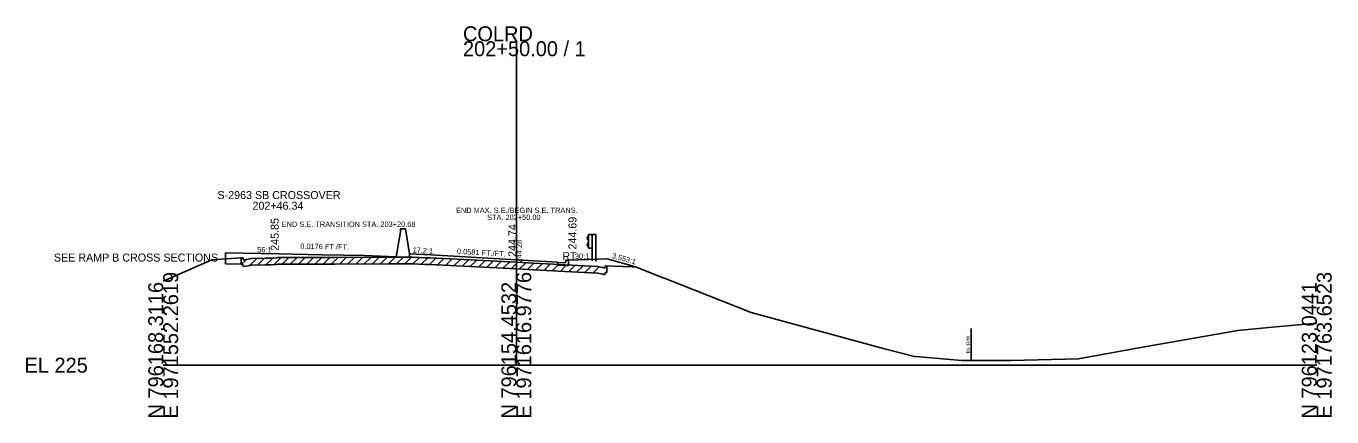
# Model space of a CAD drawing. Extents: x -26 to 1971520, y -10 to 796285.
# Drawn here: x 1274.3 to 1519, y 490.3 to 563.6 of the extents above; entities that cross this region are included whole.
import ezdxf

# ---------------------------------------------------------------- set-up
doc = ezdxf.new("R2010")
doc.units = 0
for name, color, linetype in [('RD_GPK_XS_Cell', 7, 'Continuous'), ('RD_XS_Base', 7, 'Continuous'), ('RD_XS_CurbBase', 7, 'Continuous'), ('RD_XS_CurbTop', 7, 'Continuous'), ('RD_XS_ExGround', 7, 'Continuous'), ('RD_XS_ExPaveRet', 7, 'Continuous'), ('RD_XS_ExRW', 7, 'Continuous'), ('RD_XS_GR', 7, 'Continuous'), ('RD_XS_MedBWall', 7, 'Continuous'), ('RD_XS_Misc_Line', 7, 'Continuous'), ('RD_XS_Pave', 7, 'Continuous'), ('RD_XS_PaveOvlay', 7, 'Continuous'), ('RD_XS_PaveShd', 7, 'Continuous'), ('RD_XS_TieSlope', 7, 'Continuous'), ('RD_XS_TX_Elev_EX', 7, 'Continuous'), ('RD_XS_TX_Elev_PR', 7, 'Continuous'), ('RD_XS_TX_MkPT', 7, 'Continuous'), ('RD_XS_TX_Notes', 7, 'Continuous'), ('RD_XS_TX_Slope', 7, 'Continuous'), ('RD_XS_TX_Station', 7, 'Continuous'), ('RD_XS_TX_TOC', 7, 'Continuous')]:
    doc.layers.add(name, color=color, linetype=linetype)

msp = doc.modelspace()

# ---------------------------------------------------------------- linework, layer by layer
at = {"layer": 'RD_GPK_XS_Cell'}
for p, q in [((1366.18, 500), (1366.18, 560.72)), ((1300, 500), (1366.18, 500)), ((1366.18, 500), (1516.18, 500))]:
    msp.add_line(p, q, dxfattribs=at)
at = {"layer": 'RD_XS_Base'}
for p, q in [((1311.65, 518.99), (1311.65, 521.03)), ((1314.62, 518.94), (1311.65, 518.99)), ((1373.94, 519.27), (1373.94, 519.29)), ((1373.94, 518.77), (1373.94, 519.27))]:
    msp.add_line(p, q, dxfattribs=at)
at = {"layer": 'RD_XS_CurbBase'}
for p, q in [((1375.95, 519.68), (1375.95, 518.68)), ((1375.37, 518.68), (1373.94, 518.77)), ((1375.95, 518.68), (1375.37, 518.68))]:
    msp.add_line(p, q, dxfattribs=at)
at = {"layer": 'RD_XS_CurbTop'}
for p, q in [((1373.94, 519.29), (1373.94, 519.27)), ((1373.94, 519.27), (1375.37, 519.18)), ((1375.37, 519.18), (1375.45, 519.68)), ((1375.45, 519.68), (1375.95, 519.68))]:
    msp.add_line(p, q, dxfattribs=at)
at = {"layer": 'RD_XS_ExGround'}
msp.add_lwpolyline([(1300, 515.77), (1309.13, 519.77), (1313.74, 520.04), (1314.94, 520.15), (1315.04, 519.75), (1315.9, 519.88), (1316.57, 519.98), (1319.13, 520.06), (1320.23, 520.08), (1321.24, 520.1), (1321.47, 520.17), (1322.44, 520.18), (1325.61, 520.17), (1332.18, 520.19), (1342.49, 520.22), (1344.17, 520.24), (1346.7, 520.22), (1349.11, 520.15), (1349.89, 520.14), (1353.81, 519.93), (1356.32, 519.79), (1366.18, 519.28), (1369.37, 519.11), (1373.11, 518.91), (1374, 518.86), (1381.48, 518.47), (1382.38, 518.29), (1382.74, 518.21), (1382.84, 518.61), (1387.87, 518.45), (1388.5, 518.43), (1393.67, 516.39), (1394.08, 516.23), (1410.18, 509.86), (1435.2, 503.07), (1440.79, 501.61), (1441.74, 501.55), (1449.66, 500.86), (1458.93, 500.86), (1471.54, 501.18), (1482.85, 503.24), (1501.4, 506.53), (1507.19, 507.06), (1508.54, 507.18), (1516.18, 507.9)], dxfattribs=at)
at = {"layer": 'RD_XS_ExPaveRet'}
for p, q in [((1314.62, 518.87), (1314.62, 520.12)), ((1314.62, 518.87), (1314.94, 518.9)), ((1314.94, 518.9), (1315.04, 518.5)), ((1316.57, 518.73), (1319.13, 518.81)), ((1319.13, 518.81), (1320.23, 518.83)), ((1320.23, 518.83), (1321.24, 518.85)), ((1321.24, 518.85), (1321.47, 518.92)), ((1321.47, 518.92), (1322.44, 518.93)), ((1322.44, 518.93), (1325.61, 518.92)), ((1325.61, 518.92), (1332.18, 518.94)), ((1332.18, 518.94), (1342.49, 518.97)), ((1342.49, 518.97), (1344.17, 518.99)), ((1344.17, 518.99), (1346.7, 518.97)), ((1346.7, 518.97), (1349.11, 518.9)), ((1349.11, 518.9), (1349.89, 518.89)), ((1349.89, 518.89), (1353.81, 518.68)), ((1315.04, 518.5), (1315.9, 518.63)), ((1315.9, 518.63), (1316.57, 518.73)), ((1353.81, 518.68), (1356.32, 518.54)), ((1356.32, 518.54), (1366.18, 518.03)), ((1366.18, 518.03), (1369.37, 517.86)), ((1369.37, 517.86), (1373.11, 517.66)), ((1373.11, 517.66), (1374, 517.61)), ((1374, 517.61), (1381.48, 517.22)), ((1381.48, 517.22), (1382.38, 517.04)), ((1382.38, 517.04), (1382.74, 516.96)), ((1382.74, 516.96), (1382.84, 517.36)), ((1382.84, 517.36), (1383.13, 517.35)), ((1383.13, 518.6), (1383.13, 517.35))]:
    msp.add_line(p, q, dxfattribs=at)
at = {"layer": 'RD_XS_ExRW'}
msp.add_line((1451.41, 506.86), (1451.41, 500.86), dxfattribs=at)
at = {"layer": 'RD_XS_GR'}
for p, q in [((1379.72, 524.34), (1379.45, 523.9)), ((1379.45, 523.9), (1379.45, 523.79)), ((1379.45, 523.79), (1379.72, 523.35)), ((1379.72, 524.5), (1380.39, 524.5)), ((1379.72, 521.93), (1379.72, 524.5)), ((1380.39, 524.5), (1381.05, 524.5)), ((1380.39, 524.5), (1380.39, 519.55)), ((1381.05, 524.5), (1381.05, 519.44)), ((1379.45, 522.64), (1379.72, 523.08)), ((1379.45, 522.53), (1379.45, 522.64)), ((1379.72, 522.09), (1379.45, 522.53)), ((1379.72, 521.93), (1380.39, 521.93))]:
    msp.add_line(p, q, dxfattribs=at)
at = {"layer": 'RD_XS_MedBWall'}
for p, q in [((1343.69, 520.33), (1344.44, 524.99)), ((1345.43, 525.57), (1344.44, 525.57)), ((1344.44, 525.57), (1344.44, 524.99)), ((1346.18, 520.9), (1345.43, 525.57)), ((1343.69, 520.33), (1343.69, 520.23)), ((1343.69, 520.23), (1344.17, 520.24)), ((1344.17, 520.24), (1345.43, 520.23)), ((1345.43, 520.23), (1346.18, 520.23)), ((1346.18, 520.9), (1346.18, 520.23))]:
    msp.add_line(p, q, dxfattribs=at)
at = {"layer": 'RD_XS_Misc_Line'}
for p, q in [((1314.62, 518.87), (1315.61, 519.84)), ((1316.16, 518.67), (1317.53, 520.01)), ((1317.69, 518.77), (1319, 520.05)), ((1319.22, 518.81), (1320.52, 520.08)), ((1320.75, 518.84), (1322.13, 520.18)), ((1322.29, 518.93), (1323.56, 520.18)), ((1323.82, 518.93), (1325.09, 520.17)), ((1325.35, 518.92), (1326.63, 520.17)), ((1326.89, 518.92), (1328.17, 520.18)), ((1328.42, 518.93), (1329.7, 520.18)), ((1329.95, 518.93), (1331.23, 520.19)), ((1331.48, 518.94), (1332.77, 520.19)), ((1333.02, 518.94), (1334.3, 520.2)), ((1334.55, 518.95), (1335.83, 520.2)), ((1336.08, 518.95), (1337.36, 520.2)), ((1337.62, 518.96), (1338.9, 520.21)), ((1339.15, 518.96), (1340.43, 520.21)), ((1340.68, 518.96), (1341.96, 520.22)), ((1342.21, 518.97), (1343.5, 520.23)), ((1343.75, 518.98), (1345.02, 520.23)), ((1345.28, 518.98), (1346.55, 520.22)), ((1346.81, 518.97), (1348.05, 520.18)), ((1348.34, 518.93), (1349.59, 520.15)), ((1349.88, 518.89), (1351.09, 520.08)), ((1351.41, 518.81), (1352.62, 519.99)), ((1352.94, 518.72), (1354.15, 519.91)), ((1354.48, 518.64), (1355.69, 519.83)), ((1356.01, 518.56), (1357.22, 519.75)), ((1357.54, 518.48), (1358.75, 519.67)), ((1359.07, 518.4), (1360.29, 519.59)), ((1360.61, 518.32), (1361.82, 519.51)), ((1362.14, 518.24), (1363.35, 519.43)), ((1363.67, 518.16), (1364.89, 519.34)), ((1365.21, 518.08), (1366.42, 519.26)), ((1366.74, 518), (1367.95, 519.18)), ((1368.27, 517.92), (1369.48, 519.1)), ((1369.8, 517.84), (1371.02, 519.02)), ((1371.34, 517.76), (1372.55, 518.94)), ((1372.87, 517.68), (1374.08, 518.86)), ((1374.4, 517.59), (1375.61, 518.78)), ((1375.94, 517.51), (1377.15, 518.7)), ((1377.47, 517.43), (1378.68, 518.62)), ((1379, 517.35), (1380.21, 518.54)), ((1380.53, 517.27), (1381.71, 518.42))]:
    msp.add_line(p, q, dxfattribs=at)
at = {"layer": 'RD_XS_Pave'}
for p, q in [((1321.65, 520.85), (1329.82, 520.71)), ((1329.82, 520.71), (1337.68, 520.57)), ((1350.18, 520.67), (1366.18, 519.74)), ((1366.18, 519.74), (1373.94, 519.29))]:
    msp.add_line(p, q, dxfattribs=at)
at = {"layer": 'RD_XS_PaveOvlay'}
for p, q in [((1314.62, 520.12), (1314.94, 520.15)), ((1314.62, 520.12), (1314.62, 518.94)), ((1314.94, 520.15), (1315.04, 519.75)), ((1315.04, 519.75), (1315.9, 519.88)), ((1315.9, 519.88), (1316.57, 519.98)), ((1316.57, 519.98), (1319.13, 520.06)), ((1319.13, 520.06), (1320.23, 520.08)), ((1320.23, 520.08), (1321.24, 520.1)), ((1321.24, 520.1), (1321.47, 520.17)), ((1321.47, 520.17), (1322.44, 520.18)), ((1322.44, 520.18), (1325.61, 520.17)), ((1325.61, 520.17), (1332.18, 520.19)), ((1332.18, 520.19), (1342.49, 520.22)), ((1342.49, 520.22), (1344.17, 520.24)), ((1344.17, 520.24), (1346.7, 520.22)), ((1346.7, 520.22), (1349.11, 520.15)), ((1349.11, 520.15), (1349.89, 520.14)), ((1349.89, 520.14), (1353.81, 519.93)), ((1353.81, 519.93), (1356.32, 519.79)), ((1356.32, 519.79), (1366.18, 519.28)), ((1366.18, 519.28), (1369.37, 519.11)), ((1369.37, 519.11), (1373.11, 518.91)), ((1373.11, 518.91), (1373.94, 518.87))]:
    msp.add_line(p, q, dxfattribs=at)
at = {"layer": 'RD_XS_PaveShd'}
for p, q in [((1321.65, 520.85), (1311.65, 521.03)), ((1337.68, 520.57), (1343.69, 520.33)), ((1350.18, 520.67), (1346.18, 520.9))]:
    msp.add_line(p, q, dxfattribs=at)
at = {"layer": 'RD_XS_TieSlope'}
for p, q in [((1375.95, 519.68), (1383.2, 519.93)), ((1383.2, 519.93), (1388.5, 518.43))]:
    msp.add_line(p, q, dxfattribs=at)

# ---------------------------------------------------------------- texts
at = {"layer": 'RD_GPK_XS_Cell'}
for s, p in [('COLRD', (1356.18, 560.72)), ('202+50.00 / 1', (1356.18, 557.92)), ('EL 225', (1274, 498.6))]:
    msp.add_text(s, height=2.8, dxfattribs=at).set_placement(p)
for s, p in [('E 1971552.2619', (1302.8, 490)), ('E 1971616.9776', (1368.98, 490)), ('E 1971763.6523', (1518.98, 490)), ('N 796168.3116', (1300, 490)), ('N 796154.4532', (1366.18, 490)), ('N 796123.0441', (1516.18, 490))]:
    msp.add_text(s, height=2.8, rotation=90, dxfattribs=at).set_placement(p)
at = {"layer": 'RD_XS_ExRW'}
msp.add_text('Ex. R/W ', height=0.65, rotation=90, dxfattribs=at).set_placement((1451.16, 502.24))
at = {"layer": 'RD_XS_TX_Elev_EX'}
msp.add_text('244.28', height=1, rotation=90, dxfattribs=at).set_placement((1367.18, 519.28))
at = {"layer": 'RD_XS_TX_Elev_PR'}
for s, p in [(' 245.85', (1321.65, 520.89)), (' 244.74', (1366.18, 519.74))]:
    msp.add_text(s, height=1.5, rotation=90, dxfattribs=at).set_placement(p)
at = {"layer": 'RD_XS_TX_MkPT'}
msp.add_text('RT', height=1.5, dxfattribs=at).set_placement((1374.8, 519.68))
at = {"layer": 'RD_XS_TX_Notes'}
for s, height, p in [('END MAX. S.E./BEGIN S.E. TRANS.', 1, (1354.87, 528.53)), ('END S.E. TRANSITION STA. 203+20.68', 1, (1322.22, 525.92)), ('STA. 202+50.00', 1, (1360.7, 527.22)), ('SEE RAMP B CROSS SECTIONS', 1.5, (1279.52, 519.42))]:
    msp.add_text(s, height=height, dxfattribs=at).set_placement(p)
at = {"layer": 'RD_XS_TX_Slope'}
for s, rotation, p in [('56:1', 358.9765, (1317.59, 521.17)), ('0.0176 FT./FT.', 358.9935, (1325.69, 521.82)), ('17.2:1', 356.6749, (1346.72, 521.12)), ('0.0581 FT./FT.', 356.6759, (1355.04, 520.88)), ('30:1', 1.1458, (1377.17, 519.9)), ('3.553:1', 344.2778, (1384.02, 520.11))]:
    msp.add_text(s, height=1, rotation=rotation, dxfattribs=at).set_placement(p)
at = {"layer": 'RD_XS_TX_Station'}
for s, p in [('S-2963 SB CROSSOVER', (1310.17, 531.14)), ('202+46.34', (1316.73, 529.14))]:
    msp.add_text(s, height=1.5, dxfattribs=at).set_placement(p)
at = {"layer": 'RD_XS_TX_TOC'}
msp.add_text('244.69', height=1.5, rotation=90, dxfattribs=at).set_placement((1377.45, 521.68))

doc.saveas('drawing.dxf')
